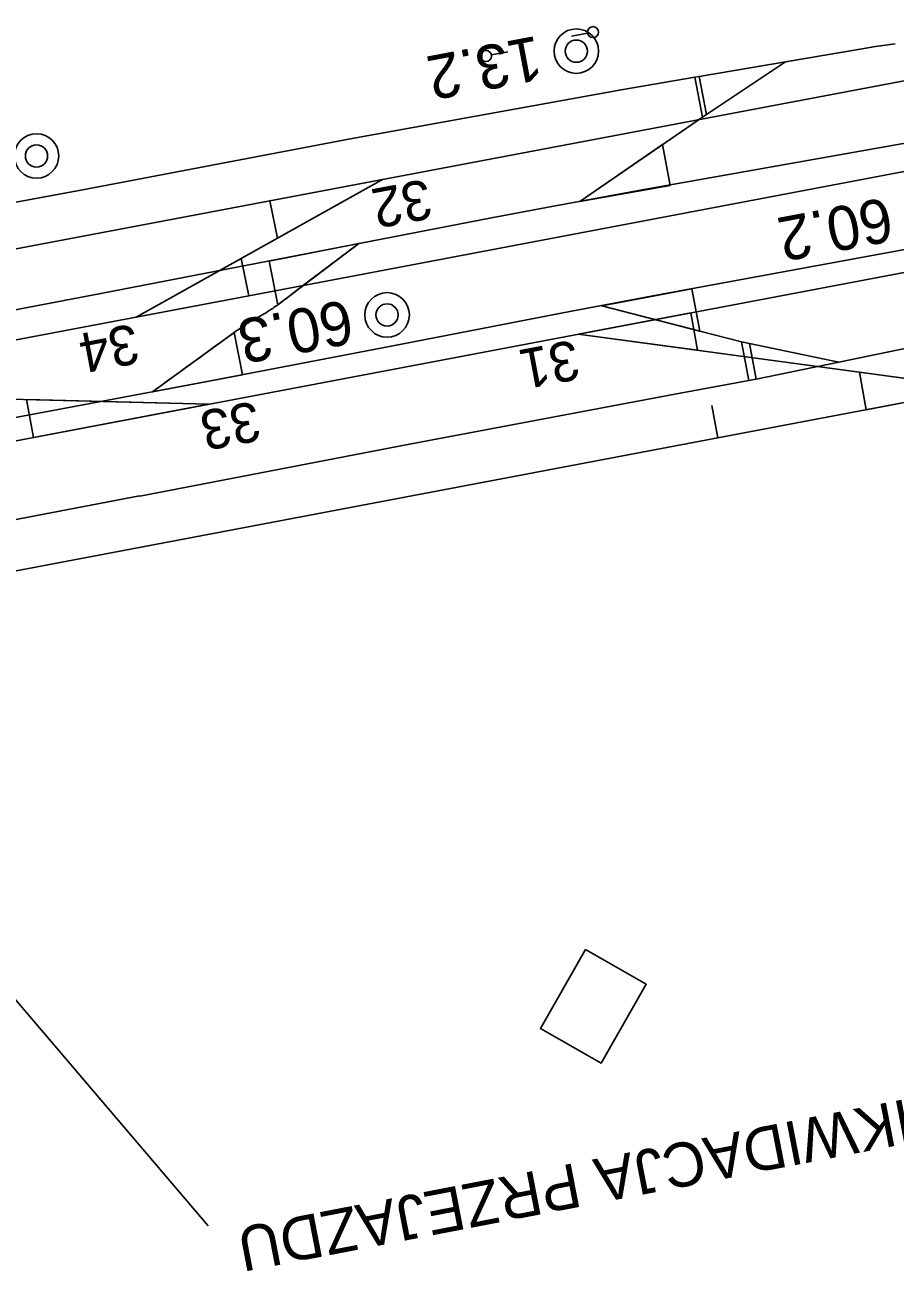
# Model space of a CAD drawing. Extents: x 6541740 to 6566395, y 5525066 to 5530361.
# Drawn here: x 6557479.1 to 6557518.5, y 5526176.6 to 5526233.1 of the extents above; entities that cross this region are included whole.
import ezdxf

# ---------------------------------------------------------------- set-up
doc = ezdxf.new("R2010")
doc.units = 0
for name, color, linetype in [('Domyślna', 7, 'Continuous'), ('ps_wymiarowanie', 7, 'Continuous'), ('TOR_PRZEK_P-komponent', 7, 'Continuous'), ('TOR_PRZEK_P-teren istniejacy', 7, 'Continuous'), ('TOR_PS_ODW-drenokolektory', 7, 'Continuous'), ('TOR_PS_ODW-kolektory', 7, 'Continuous'), ('TOR_PS_OPIS_O-opisy odwodnienia', 7, 'Continuous'), ('TOR_PS_P-ogrodzenia', 7, 'Continuous'), ('TOR_PS_T-rowy otwarte nieumocnione', 7, 'Continuous'), ('TOR_RAMKI-ramka+tabelka 1', 7, 'Continuous')]:
    doc.layers.add(name, color=color, linetype=linetype)

# ---------------------------------------------------------------- blocks, each defined once
blk = doc.blocks.new('4010_1')
at = {"layer": 'Domyślna'}
for radius in [0.75, 0.375]:
    blk.add_circle((0, 0), radius, dxfattribs=at)
blk = doc.blocks.new('4302_9')
at = {"layer": 'Domyślna'}
blk.add_line((0.246, -0.009), (0.996, -0.009), dxfattribs=at)
blk.add_circle((-0.004, -0.009), 0.25, dxfattribs=at)
blk = doc.blocks.new('POINT_DISPLAY')
at = {"layer": 'Domyślna'}
blk.add_line((0, 0), (0, 0), dxfattribs=at)
blk = doc.blocks.new('4302_7')
at = {"layer": 'Domyślna'}
blk.add_line((0.25, 0), (1, 0), dxfattribs=at)
blk.add_circle((0, 0), 0.25, dxfattribs=at)
blk.add_blockref('POINT_DISPLAY', (0, 0), dxfattribs=at)

msp = doc.modelspace()

# ---------------------------------------------------------------- linework, layer by layer
at = {"layer": 'ps_wymiarowanie'}
msp.add_lwpolyline([(6557504.484, 5526191.144), (6557507.236, 5526189.574), (6557505.193, 5526185.993), (6557502.441, 5526187.563), (6557504.484, 5526191.144)], close=True, dxfattribs=at)
at = {"layer": 'TOR_PRZEK_P-komponent'}
for p, q in [((6557431.345, 5526213.97), (6557890.08, 5526300.925)), ((6557887.094, 5526296.236), (6557489.207, 5526220.816)), ((6557816.588, 5526278.292), (6557431.956, 5526205.384)), ((6557495.282, 5526226.089), (6557484.099, 5526219.848)), ((6557489.207, 5526220.816), (6557454.473, 5526214.232)), ((6557522.333, 5526216.612), (6557504.157, 5526219.07)), ((6557531.024, 5526218.259), (6557427.941, 5526198.719)), ((6557487.404, 5526215.894), (6557466.118, 5526216.439))]:
    msp.add_line(p, q, dxfattribs=at)
at = {"layer": 'TOR_PRZEK_P-teren istniejacy'}
msp.add_lwpolyline([(6557487.369, 5526178.618), (6557463.881, 5526206.166)], dxfattribs=at)
at = {"layer": 'TOR_PS_ODW-drenokolektory'}
msp.add_line((6557511.925, 5526218.647), (6557511.569, 5526218.721), dxfattribs=at)
msp.add_line((6557511.925, 5526218.647), (6557511.569, 5526218.721), dxfattribs=at)
at = {"layer": 'TOR_PS_ODW-kolektory'}
msp.add_line((6557510.214, 5526215.841), (6557510.493, 5526214.367), dxfattribs=at)
msp.add_line((6557510.214, 5526215.841), (6557510.493, 5526214.367), dxfattribs=at)
at = {"layer": 'TOR_PS_P-ogrodzenia'}
for p, q in [((6557490.174, 5526225.121), (6557495.282, 5526226.09)), ((6557489.207, 5526220.816), (6557484.099, 5526219.848)), ((6557509.266, 5526220.038), (6557504.157, 5526219.07)), ((6557517.225, 5526215.643), (6557522.333, 5526216.612)), ((6557487.404, 5526215.894), (6557479.444, 5526214.385))]:
    msp.add_line(p, q, dxfattribs=at)
for points in [[(6557495.282, 5526226.09), (6557490.513, 5526223.428), (6557490.174, 5526225.121)], [(6557484.099, 5526219.848), (6557488.868, 5526222.509), (6557489.207, 5526220.816)], [(6557504.157, 5526219.07), (6557509.57, 5526218.338), (6557509.266, 5526220.038)], [(6557522.333, 5526216.612), (6557516.921, 5526217.344), (6557517.225, 5526215.643)], [(6557479.444, 5526214.385), (6557479.129, 5526216.106), (6557487.404, 5526215.894)]]:
    msp.add_lwpolyline(points, dxfattribs=at)
at = {"layer": 'TOR_PS_T-rowy otwarte nieumocnione'}
for p, q in [((6557504.233, 5526225.087), (6557509.795, 5526228.92)), ((6557504.233, 5526225.087), (6557509.795, 5526228.92)), ((6557509.968, 5526229.036), (6557509.795, 5526228.92)), ((6557509.968, 5526229.036), (6557509.795, 5526228.92)), ((6557493.897, 5526227.948), (6557481.593, 5526225.605)), ((6557493.897, 5526227.948), (6557481.593, 5526225.605)), ((6557505.229, 5526220.358), (6557509.676, 5526219.206)), ((6557505.229, 5526220.358), (6557509.676, 5526219.206)), ((6557505.229, 5526220.358), (6557509.676, 5526219.206)), ((6557505.229, 5526220.358), (6557509.676, 5526219.206)), ((6557511.925, 5526218.647), (6557511.569, 5526218.721)), ((6557511.925, 5526218.647), (6557511.569, 5526218.721)), ((6557515.972, 5526217.801), (6557511.925, 5526218.647)), ((6557515.972, 5526217.801), (6557511.925, 5526218.647)), ((6557496.497, 5526214.083), (6557484.262, 5526211.724)), ((6557496.497, 5526214.083), (6557484.262, 5526211.724))]:
    msp.add_line(p, q, dxfattribs=at)
for points in [[(6557548.233, 5526232.921), (6557507.053, 5526225.613), (6557502.954, 5526224.859), (6557500.224, 5526224.343), (6557494.768, 5526223.29), (6557494.768, 5526223.29), (6557482.503, 5526220.91), (6557482.503, 5526220.91), (6557470.214, 5526218.569), (6557470.214, 5526218.569), (6557457.942, 5526216.211), (6557457.941, 5526216.211), (6557445.676, 5526213.923), (6557445.676, 5526213.923), (6557433.375, 5526211.597), (6557433.375, 5526211.597), (6557421.103, 5526209.266)], [(6557548.233, 5526232.921), (6557507.053, 5526225.613), (6557502.954, 5526224.859), (6557500.224, 5526224.343), (6557494.768, 5526223.29), (6557494.768, 5526223.29), (6557482.503, 5526220.91), (6557482.503, 5526220.91), (6557470.214, 5526218.569), (6557470.214, 5526218.569), (6557457.942, 5526216.211), (6557457.941, 5526216.211), (6557445.676, 5526213.923), (6557445.676, 5526213.923), (6557433.375, 5526211.597), (6557433.375, 5526211.597), (6557421.103, 5526209.266)], [(6557517.647, 5526232.116), (6557517.04, 5526232.014), (6557513.655, 5526231.442), (6557509.642, 5526230.765)], [(6557517.647, 5526232.116), (6557517.04, 5526232.014), (6557513.655, 5526231.442), (6557509.642, 5526230.765)], [(6557518.529, 5526232.248), (6557517.647, 5526232.116)], [(6557518.529, 5526232.248), (6557517.647, 5526232.116)], [(6557509.453, 5526230.733), (6557506.196, 5526230.174), (6557493.896, 5526227.947)], [(6557509.453, 5526230.733), (6557506.196, 5526230.174), (6557493.896, 5526227.947)], [(6557549.068, 5526228.442), (6557507.95, 5526220.893), (6557507.949, 5526220.893), (6557503.851, 5526220.121), (6557495.664, 5526218.533), (6557495.664, 5526218.533), (6557487.481, 5526216.958), (6557482.022, 5526215.923), (6557471.101, 5526213.881), (6557471.1, 5526213.881), (6557462.933, 5526212.375), (6557458.848, 5526211.63), (6557458.848, 5526211.63), (6557450.61, 5526210.135), (6557446.494, 5526209.377), (6557442.394, 5526208.608), (6557434.2, 5526207.039), (6557434.2, 5526207.039), (6557421.947, 5526204.68)], [(6557549.068, 5526228.442), (6557507.95, 5526220.893), (6557507.949, 5526220.893), (6557503.851, 5526220.121), (6557495.664, 5526218.533), (6557495.664, 5526218.533), (6557487.481, 5526216.958), (6557482.022, 5526215.923), (6557471.101, 5526213.881), (6557471.1, 5526213.881), (6557462.933, 5526212.375), (6557458.848, 5526211.63), (6557458.848, 5526211.63), (6557450.61, 5526210.135), (6557446.494, 5526209.377), (6557442.394, 5526208.608), (6557434.2, 5526207.039), (6557434.2, 5526207.039), (6557421.947, 5526204.68)], [(6557456.992, 5526220.972), (6557469.32, 5526223.338), (6557481.593, 5526225.605)], [(6557456.992, 5526220.972), (6557469.32, 5526223.338), (6557481.593, 5526225.605)], [(6557511.569, 5526218.721), (6557509.676, 5526219.206)], [(6557511.569, 5526218.721), (6557509.676, 5526219.206)], [(6557520.043, 5526218.631), (6557519.569, 5526218.534), (6557515.973, 5526217.798), (6557512.229, 5526217.032)], [(6557520.043, 5526218.631), (6557519.569, 5526218.534), (6557515.973, 5526217.798), (6557512.229, 5526217.032)], [(6557511.903, 5526216.965), (6557508.779, 5526216.392), (6557496.499, 5526214.083)], [(6557511.903, 5526216.965), (6557508.779, 5526216.392), (6557496.499, 5526214.083)], [(6557512.229, 5526217.032), (6557512.209, 5526217.028), (6557511.903, 5526216.965)], [(6557512.229, 5526217.032), (6557512.209, 5526217.028), (6557511.903, 5526216.965)], [(6557459.776, 5526206.984), (6557463.245, 5526207.651), (6557463.582, 5526207.718), (6557471.937, 5526209.37), (6557484.261, 5526211.729)], [(6557459.776, 5526206.984), (6557463.245, 5526207.651), (6557463.582, 5526207.718), (6557471.937, 5526209.37), (6557484.261, 5526211.729)]]:
    msp.add_lwpolyline(points, dxfattribs=at)
for points in [[(6557513.552, 5526231.426), (6557509.642, 5526230.765), (6557509.968, 5526229.036)], [(6557513.552, 5526231.426), (6557509.642, 5526230.765), (6557509.968, 5526229.036)], [(6557509.968, 5526229.036), (6557509.642, 5526230.765), (6557509.453, 5526230.733), (6557509.795, 5526228.92)], [(6557509.968, 5526229.036), (6557509.642, 5526230.765), (6557509.453, 5526230.733), (6557509.795, 5526228.92)], [(6557504.233, 5526225.087), (6557508.322, 5526225.82), (6557507.973, 5526227.672)], [(6557504.233, 5526225.087), (6557508.322, 5526225.82), (6557507.973, 5526227.672)], [(6557494.204, 5526223.181), (6557490.134, 5526222.384), (6557490.527, 5526220.399)], [(6557494.204, 5526223.181), (6557490.134, 5526222.384), (6557490.527, 5526220.399)], [(6557505.229, 5526220.358), (6557509.31, 5526221.129), (6557509.676, 5526219.206)], [(6557505.229, 5526220.358), (6557509.31, 5526221.129), (6557509.676, 5526219.206)], [(6557484.843, 5526216.458), (6557488.923, 5526217.233), (6557488.554, 5526219.15)], [(6557484.843, 5526216.458), (6557488.923, 5526217.233), (6557488.554, 5526219.15)], [(6557511.925, 5526218.647), (6557512.229, 5526217.032), (6557511.903, 5526216.965), (6557511.569, 5526218.721)], [(6557511.925, 5526218.647), (6557512.229, 5526217.032), (6557511.903, 5526216.965), (6557511.569, 5526218.721)], [(6557515.972, 5526217.801), (6557512.229, 5526217.032), (6557511.925, 5526218.647)], [(6557515.972, 5526217.801), (6557512.229, 5526217.032), (6557511.925, 5526218.647)]]:
    msp.add_lwpolyline(points, close=True, dxfattribs=at)
for points in [[(6557494.204, 5526223.181), (6557493.589, 5526222.72), (6557492.974, 5526222.264), (6557492.36, 5526221.8), (6557491.748, 5526221.337), (6557491.138, 5526220.866), (6557490.527, 5526220.399)], [(6557494.204, 5526223.181), (6557493.589, 5526222.72), (6557492.974, 5526222.264), (6557492.36, 5526221.8), (6557491.748, 5526221.337), (6557491.138, 5526220.866), (6557490.527, 5526220.399)], [(6557494.204, 5526223.181), (6557493.589, 5526222.72), (6557492.974, 5526222.264), (6557492.36, 5526221.8), (6557491.748, 5526221.337), (6557491.138, 5526220.866), (6557490.527, 5526220.399)], [(6557494.204, 5526223.181), (6557493.589, 5526222.72), (6557492.974, 5526222.264), (6557492.36, 5526221.8), (6557491.748, 5526221.337), (6557491.138, 5526220.866), (6557490.527, 5526220.399)], [(6557484.843, 5526216.458), (6557486.08, 5526217.355), (6557487.317, 5526218.253), (6557488.554, 5526219.15), (6557489.192, 5526219.613), (6557489.859, 5526219.942), (6557490.502, 5526220.381), (6557490.51, 5526220.387), (6557490.519, 5526220.393), (6557490.527, 5526220.399)], [(6557484.843, 5526216.458), (6557486.08, 5526217.355), (6557487.317, 5526218.253), (6557488.554, 5526219.15), (6557489.192, 5526219.613), (6557489.859, 5526219.942), (6557490.502, 5526220.381), (6557490.51, 5526220.387), (6557490.519, 5526220.393), (6557490.527, 5526220.399)], [(6557484.843, 5526216.458), (6557486.08, 5526217.355), (6557487.317, 5526218.253), (6557488.554, 5526219.15), (6557489.192, 5526219.613), (6557489.859, 5526219.942), (6557490.502, 5526220.381), (6557490.51, 5526220.387), (6557490.519, 5526220.393), (6557490.527, 5526220.399)], [(6557484.843, 5526216.458), (6557486.08, 5526217.355), (6557487.317, 5526218.253), (6557488.554, 5526219.15), (6557489.192, 5526219.613), (6557489.859, 5526219.942), (6557490.502, 5526220.381), (6557490.51, 5526220.387), (6557490.519, 5526220.393), (6557490.527, 5526220.399)]]:
    msp.add_open_spline(points, degree=3, dxfattribs=at)

# ---------------------------------------------------------------- block references
at = {"layer": 'Domyślna'}
for name, p, rotation in [('4302_9', (6557504.825, 5526232.765), -169.58637404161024), ('4302_9', (6557504.825, 5526232.765), -169.58637404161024), ('4302_7', (6557499.972, 5526231.695), 10.3491395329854), ('4302_7', (6557499.972, 5526231.695), 10.3491395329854)]:
    msp.add_blockref(name, p, dxfattribs=dict(at, rotation=rotation))
at = {"layer": 'TOR_RAMKI-ramka+tabelka 1', "xscale": 1.345963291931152, "yscale": 1.345963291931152}
for p in [(6557504.07, 5526231.913), (6557479.583, 5526227.158), (6557495.486, 5526219.945)]:
    msp.add_blockref('4010_1', p, dxfattribs=at)

# ---------------------------------------------------------------- texts
at = {"layer": 'TOR_PRZEK_P-teren istniejacy'}
msp.add_text('LIKWIDACJA PRZEJAZDU', height=2, rotation=190.9433, dxfattribs=at).set_placement((6557520.519, 5526184.662))
at = {"layer": 'TOR_PS_OPIS_O-opisy odwodnienia'}
for s, p in [('32', (6557497.309, 5526226.124)), ('34', (6557484.028, 5526219.556)), ('31', (6557504.007, 5526218.828)), ('33', (6557489.533, 5526216.044))]:
    msp.add_text(s, height=1.8, rotation=190.7332, dxfattribs=at).set_placement(p)
at = {"layer": 'TOR_RAMKI-ramka+tabelka 1'}
for s, p in [('13.2', (6557502.286, 5526232.618)), ('60.2', (6557518.195, 5526225.293)), ('60.3', (6557493.712, 5526220.652))]:
    msp.add_text(s, height=2, rotation=190.7691, dxfattribs=at).set_placement(p)

doc.saveas('drawing.dxf')
